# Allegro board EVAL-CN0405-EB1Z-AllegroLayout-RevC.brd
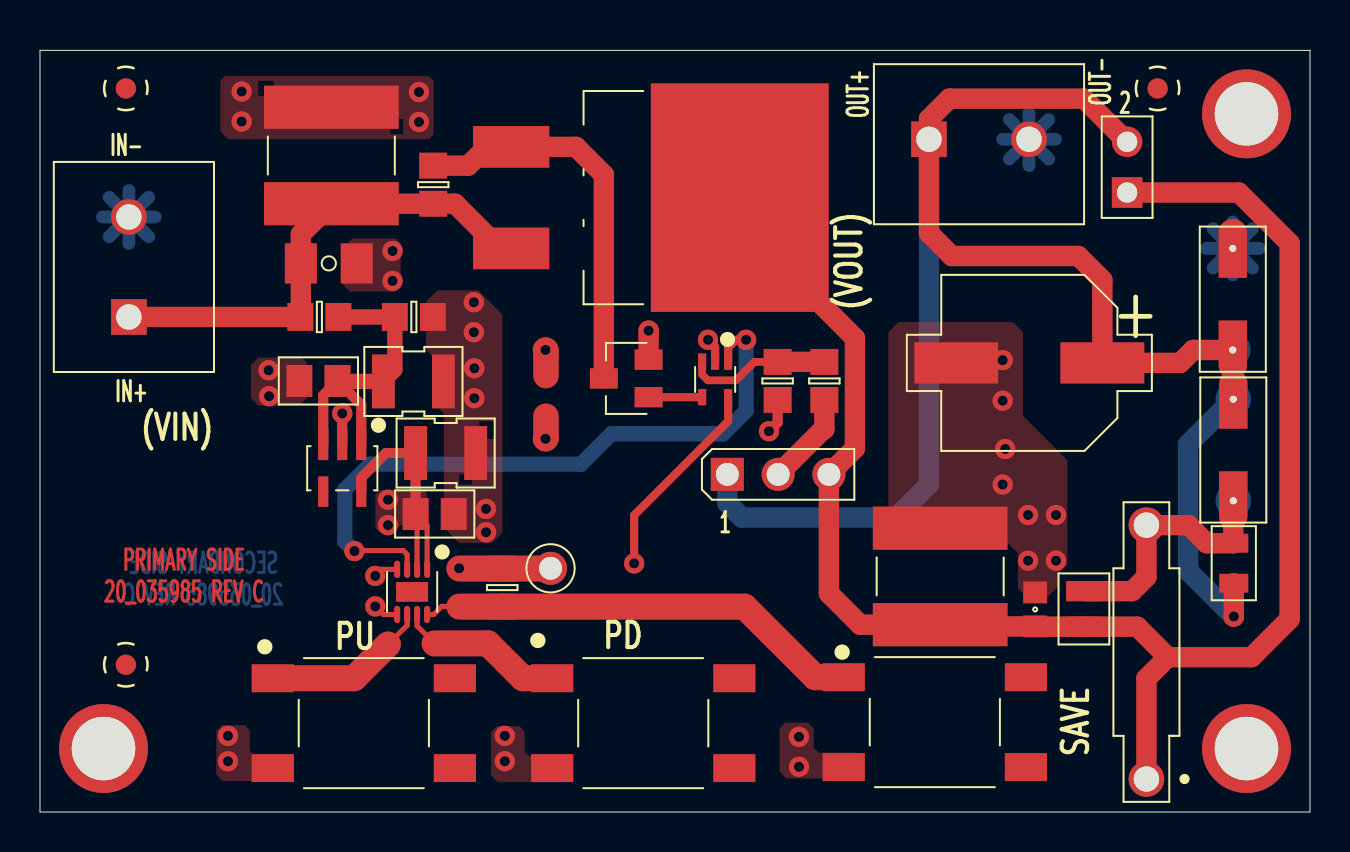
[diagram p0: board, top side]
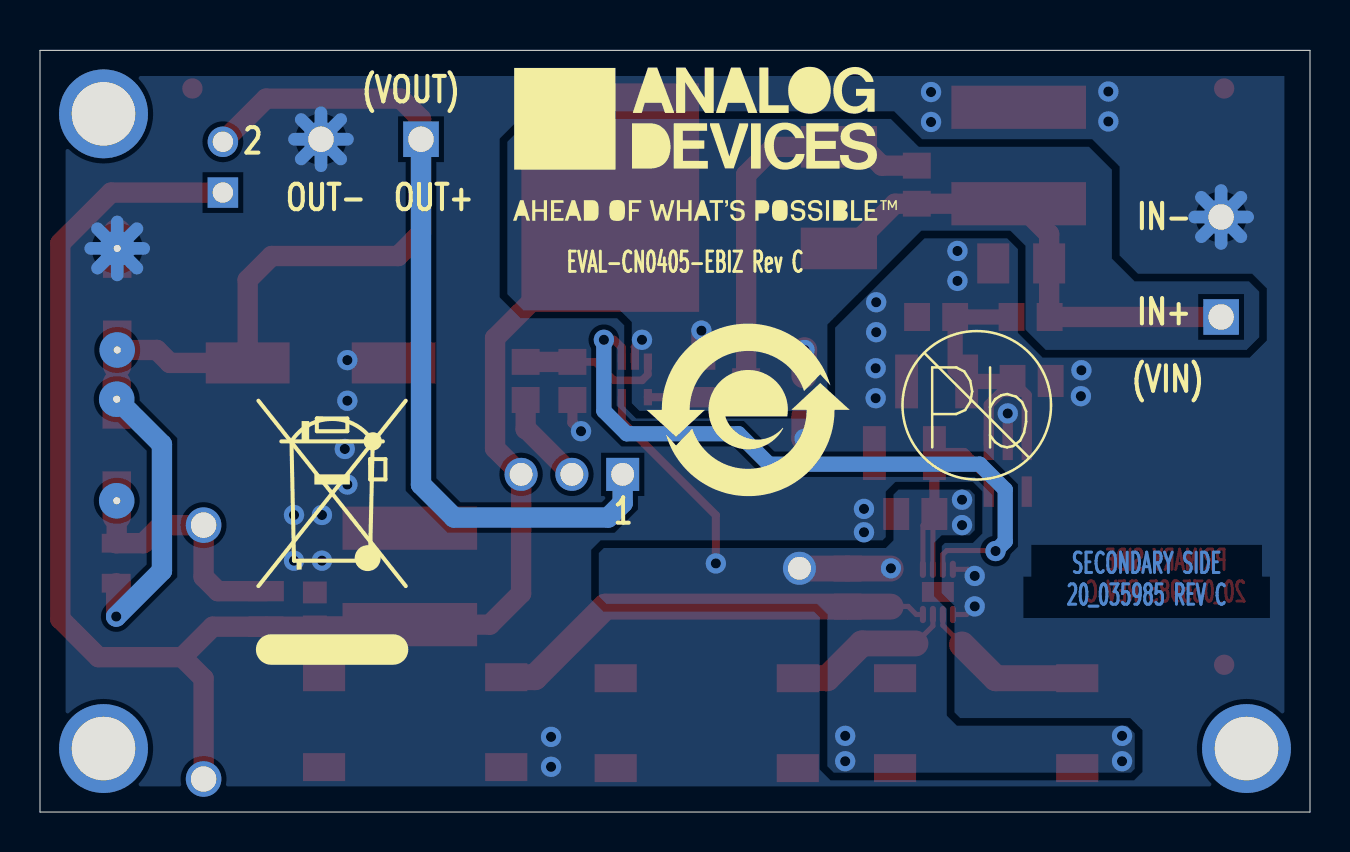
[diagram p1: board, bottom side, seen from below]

Outline 63.5 x 38.1 mm; copper layers: TOP, BOTTOM. Coordinates in mm from the lower left corner of the outline.
Outline path: 0,38.1 0,0 63.5,0 63.5,38.1 0,38.1

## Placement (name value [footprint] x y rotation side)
A1  ADCMP371AKSZ  [SC70-5]  33.76 21.64 180 top
C1  1uF  [C1210H75]  18.67 21.54 180 top
C2  0.1uF  [C0805H53]  13.92 21.56 0 top
C3  1uF  [C2225]  14.57 32.84 270 top
C4  0.1uF  [C1206H71]  14.44 27.44 180 top
C5  1uF  [C1210H75]  20.28 17.96 180 top
C6  0.1uF  [C0805H53]  19.74 14.91 180 top
C7  1uF  [C2225]  45.01 11.79 270 top
C8  0.1uF  [C0603]  49.76 10.13 90 top
C9  TBDR0805_CTH200LD25  [R0805_CTH200LD25]  59.64 28.19 270 top
C10  330UF  [CPLSMSQ327H413]  49.47 22.47 180 top
JP1  69157-102HLF  [CNBERG69157-102]  54.36 30.99 90 top
L1  330nH  [L9075]  52.2 10.16 90 top
L_G1  TBD_SPACER_500_D40  [L_SPACER_500_D40]  55.32 8 90 top
NOREF  -  []  0 36.41 0 top
NOREF#2  -  []  4.29 36.2 0 top
NOREF#3  -  []  -182.88 -240.03 0 top
NOREF#4  -  []  0 0 0 top
NOREF#5  -  []  -184.15 -241.3 0 top
NOREF#6  -  []  63.5 0 90 top
NOREF#7  -  [unnamed#2]  3.18 3.17 90 top
NOREF#8  -  [unnamed#2]  60.33 3.17 90 top
NOREF#9  -  [unnamed#2]  4.29 36.2 0 top
NOREF#10  -  [unnamed#2]  4.29 7.37 0 top
NOREF#11  -  []  32.23 51.59 0 top
NOREF#12  -  [unnamed#2]  55.88 36.2 0 top
NOREF#13  -  []  -175.26 -230.89 0 top
NOREF#14  -  []  0 38.1 270 top
NOREF#15  -  []  222 54.99 0 top
NOREF#16  -  []  63.5 0 90 top
NOREF#17  -  [unnamed#2]  60.33 34.92 90 top
NOREF#18  -  []  180.21 244.98 0 top
NOREF#19  -  []  4.29 36.2 90 top
NOREF#20  -  []  4.29 36.2 0 top
NOREF#21  -  []  -67.06 178.44 0 top
NOREF#22  -  []  63.5 38.1 180 top
NOREF#23  -  []  0 0 0 top
NOREF#24  -  []  28.09 20.12 180 bottom
NOREF#25  -  []  39.62 24.26 180 bottom
NOREF#26  -  []  30.23 33.4 180 bottom
NOREF#27  -  []  16.66 20.35 180 bottom
P1  CTB5000/2  [CN1X2H394]  4.45 24.77 90 top
P2  CTB5000/2  [CN1X2H394]  44.45 33.66 0 top
P3  TSW-103-08-G-S  [CNBERG1X3H205LD36]  34.37 16.89 0 top
Q1  BSS138LT1G  [SOT23]  29.31 21.69 90 top
Q2  IRF9630SPBF  [D2PAK]  30.54 30.73 270 top
R1  1.15K  [R0805]  13.97 24.77 180 top
R2  350  [R0805]  18.69 24.77 180 top
R3  1K  [R0805]  19.66 31.38 90 top
R4  80.6K  [R0805]  39.22 21.56 270 top
R5  13K  [R0805]  36.88 21.56 90 top
R6  100K  [R0805]  23.11 11.23 90 top
R7  TBDR0805_CTH200LD25  [R0805_CTH200LD25]  59.66 15.57 90 top
R8  50  [R0805H20]  59.69 12.45 270 top
S1  FSM8JSMAATR  [SWSMSQ236H384]  44.74 4.5 270 top
S2  FSM8JSMAATR  [SWSMSQ236H384]  30.16 4.45 270 top
S3  FSM8JSMAATR  [SWSMSQ236H384]  16.19 4.45 270 top
SNS1  SNS  [NCSNS50MIL]  25.3 19.8 90 top
TPVDD  TESTPAD  [TPC65D45]  25.53 12.19 0 top
U1  ADP121-AUJZ33  [TSOT-5]  15.11 17.2 180 top
U2  AD5116BCPZ5  [QFN8_2X2_PAD1_6X1]  18.61 11.01 180 top

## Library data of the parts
A1 = ADCMP37X: Tolerance: N/A; User Part Number: UPN; alternate symbols: (); part number: ADCMP37X_SM-ADCMP371AKSZ,E018321,SC70-5; tolerance: N/A
C1 C5 = CAP: User Part Number: UPN; Tolerance: 10; alternate symbols: (); part number: CAP_SM-1UF,50V,10,E017543,C1210H75; tolerance: 10
C2 C6 = CAP: Tolerance: 10; User Part Number: UPN; alternate symbols: (); part number: CAP_SM-0.1UF,50V,10,E010137,C0805H53; tolerance: 10
C3 C7 = CAP: Tolerance: 10; User Part Number: UPN; alternate symbols: (); part number: CAP_SM-1UF,200V,10,E012508,C2225; tolerance: 10
C4 = CAP: Tolerance: 10; User Part Number: UPN; alternate symbols: (); part number: CAP_SM-0.1UF,200V,10,E017225,C1206H71; tolerance: 10
C8 = CAP: Tolerance: 10; User Part Number: UPN; alternate symbols: (); part number: CAP_SM-0.1UF,10V,10,E018346,C0603; tolerance: 10
C9 = CAP: User Part Number: UPN; alternate symbols: (); part number: CAP_TH-TBDR0805_CTH200LD25,TBDR0805_CTH200LD25,TBDR0805_CTH200LD25,E016990,R0805_CTH200LD25
C10 = CAPP: User Part Number: UPN; Tolerance: 20; alternate symbols: (); part number: CAPP_SM-330UF,25V,20,E027963,CPLSMSQ327H413; tolerance: 20
JP1 = CNJMPRSHRT: Tolerance: N/A; User Part Number: UPN; alternate symbols: (); part number: CNJMPRSHRT_TH-69157-102HLF,E017268,CNBERG69157-102; tolerance: N/A
L1 = IND: Tolerance: 2; User Part Number: UPN; alternate symbols: (); part number: IND_SM-330NH,2,E007962,L9075; tolerance: 2
L_G1 = IND_V2: Tolerance: N/A; User Part Number: UPN; alternate symbols: (); part number: IND_V2_TH-TBD_SPACER_500_D40,N/A,E011375,L_SPACER_500_D40; tolerance: N/A
P1 P2 = CN2P: Tolerance: N/A; User Part Number: UPN; alternate symbols: (); part number: CN2P_TH-CTB5000/2,E017604,CN1X2H394; tolerance: N/A
P3 = CN3P: User Part Number: UPN; Tolerance: N/A; alternate symbols: (); part number: CN3P_TH-TSW-103-08-G-S,E000812,CNBERG1X3H205LD36; tolerance: N/A
Q1 = TRANNMOSFET_V8: User Part Number: UPN; Tolerance: N/A; alternate symbols: (); part number: TRANNMOSFET_V8_SM-BSS138LT1G,E018770,SOT23; tolerance: N/A
Q2 = TRANPMOSFET_V11: Tolerance: N/A; User Part Number: UPN; alternate symbols: (); part number: TRANPMOSFET_V11_SM-IRF9630SPBF,E020172,D2PAK; tolerance: N/A
R1 = RES: Tolerance: 1; User Part Number: UPN; alternate symbols: (); part number: RES_SM-1.15K,E003531,1/8W,1,R0805; tolerance: 1
R2 = RES: Tolerance: 0.01; User Part Number: UPN; alternate symbols: (); part number: RES_SM-350,E016531,1/5W,0.01,R0805; tolerance: 0.01
R3 = RES: Tolerance: 1; User Part Number: UPN; alternate symbols: (); part number: RES_SM-1K,E003415,1/8W,1,R0805; tolerance: 1
R4 = RES: Tolerance: 1; User Part Number: UPN; alternate symbols: (); part number: RES_SM-80.6K,E015510,1/8W,1,R0805; tolerance: 1
R5 = RES: Tolerance: 1; User Part Number: UPN; alternate symbols: (); part number: RES_SM-13K,E003507,1/8W,1,R0805; tolerance: 1
R6 = RES: Tolerance: 1; User Part Number: UPN; alternate symbols: (); part number: RES_SM-100K,E003488,1/8W,1,R0805; tolerance: 1
R7 = RES: User Part Number: UPN; alternate symbols: (); part number: RES_TH-TBDR0805_CTH200LD25,E016991,TBDR0805_CTH200LD25,TBDR0805_CTH200LD25,R0805_CTH200LD25
R8 = RES: Tolerance: 1; User Part Number: UPN; alternate symbols: (); part number: RES_SM-50,E026102,1/8W,1,R0805H20; tolerance: 1
S1-S3 = SWSPST4PIN_B: User Part Number: UPN; Tolerance: N/A; alternate symbols: (); part number: SWSPST4PIN_B_SM-FSM8JSMAATR,E018827,SWSMSQ236H384; tolerance: N/A
SNS1 = NCSENSE: User Part Number: UPN; Tolerance: N/A; alternate symbols: (); part number: NCSENSE_SM-SNS,E005619,NCSNS50MIL; tolerance: N/A
TPVDD = NCTESTPAD: Tolerance: N/A; User Part Number: UPN; alternate symbols: (); part number: NCTESTPAD_TH-TESTPAD,E013404,TPC65D45; tolerance: N/A
U1 = ADP121: User Part Number: UPN; Tolerance: N/A; alternate symbols: (); part number: ADP121_SM-ADP121-AUJZ33,E013943,TSOT-5; tolerance: N/A
U2 = AD511X: User Part Number: UPN; Tolerance: N/A; alternate symbols: (); part number: AD511X_SM-AD5116BCPZ5,E017320,QFN8_2X2_PAD1_6X1; tolerance: N/A

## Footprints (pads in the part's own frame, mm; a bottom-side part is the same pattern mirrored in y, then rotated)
C0603
  rect 1.092x1.194 smd: 1(-0.851,0) 2(0.851,0)
C0805H53
  rect 1.295x1.6 smd: 1(-0.953,0) 2(0.953,0)
C1206H71
  rect 1.6x2.007 smd: 1(-1.397,0) 2(1.397,0)
C1210H75
  rect 1.143x2.692 smd: 1(-1.501,0) 2(1.501,0)
C2225
  rect 2.159x6.731 smd: 1(-2.413,0) 2(2.413,0)
CN1X2H394
  rect 1.778x1.778 hole 1.27: 1(0,0)
  round 1.778 hole 1.27: 2(5.001,0)
CNBERG1X3H205LD36
  rect 1.651x1.651 hole 1.143: 1(0,0)
  round 1.651 hole 1.143: 2(2.54,0) 3(5.08,0)
CNBERG69157-102
  rect 1.524x1.524 hole 1.016: 1(0,0)
  round 1.524 hole 1.016: 2(2.54,0)
CPLSMSQ327H413
  rect 4.191x2.057 smd: N(3.65,0) P(-3.65,0)
D2PAK
  rect 2.083x3.81 smd: 1(-2.54,-6.985) 3(2.54,-6.985)
  rect 11.43x8.89 smd: 4(0,4.445)
L9075
  rect 1.016x1.778 smd: 1(-0.889,0) 2(0.889,0)
L_SPACER_500_D40
  round 1.778 hole 1.27: 1(-6.35,0) 2(6.35,0)
NCSNS50MIL
  round 0.127 smd: 1(0,0) 2(2.032,0)
QFN8_2X2_PAD1_6X1
  oval 0.305x0.864 smd: 1(-0.749,-1.13) 2(-0.249,-1.13) 3(0.249,-1.13) 4(0.749,-1.13) 5(0.749,1.13) 6(0.249,1.13) 7(-0.249,1.13) 8(-0.749,1.13)
  rect 1.6x0.991 smd: PAD(0,0)
R0805
  rect 1.295x1.397 smd: 1(-0.953,0) 2(0.953,0)
R0805_CTH200LD25
  custom 0.356x0.356 hole 1.27: 1(0,0) 2(5.08,0)
R0805H20
  rect 0.94x1.448 smd: 1(-1.001,0) 2(1.001,0)
SC70-5
  rect 0.406x0.813 smd: 1(-0.65,-0.889) 2(0,-0.889) 3(0.65,-0.889) 4(0.65,0.889) 5(-0.65,0.889)
SOT23
  rect 1.016x1.397 smd: 1(-0.94,-1.118) 2(0.94,-1.118) 3(0,1.118)
SWSMSQ236H384
  rect 1.397x2.108 smd: 1(-2.248,-4.554) 2(-2.248,4.554) 3(2.248,-4.554) 4(2.248,4.554)
TPC65D45
  round 1.651 hole 1.143: 1(0,0)
TSOT-5
  rect 0.508x1.524 smd: 1(-0.95,-1.171) 2(0,-1.171) 3(0.95,-1.171) 4(0.95,1.171) 5(-0.95,1.171)
unnamed#2
  round 4.445 hole 3.175 unplated: (0,0)

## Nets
AGND: C1.1(N1) C2.1(N1) C3.1(N1) C4.1(N1) C5.1(N1) C6.1(N1) C7.1(N1) C8.2(N2) C9.1(N1) C10.N(N2) P1.2(N2) P2.2(N2) R2.1(N1) R5.1(N1) S1.3(N3) SNS1.1(N1) U1.2(GND) U2.4(B) U2.5(GND)
DGND: A1.2(GND) Q1.2(S) SNS1.2(N2)
VDD: A1.5(VCC) C5.2(N2) C6.2(N2) R6.2(N2) S2.3(N3) S3.3(N3) TPVDD.1(N1) U1.5(VOUT) U2.1(VDD) U2.2(A)
ASE: R6.1(N1) S1.1(N1) U2.8(ASE_N)
PD: S3.1(N1) U2.6(PD)
PU: S2.1(N1) U2.7(PU)
UNNAMED_2_AD511X_I16_W: A1.1(IN+) U2.3(W)
UNNAMED_2_ADCMP37X_I57_IN: A1.3(IN-) R4.1(N1) R5.2(N2)
UNNAMED_2_ADCMP37X_I57_OUT: A1.4(OUT) Q1.1(G)
UNNAMED_2_ADP121_I14_EN: C1.2(N2) C2.2(N2) R1.1(N1) R2.2(N2) U1.1(VIN) U1.3(EN)
UNNAMED_2_CAP_I50_N2: C3.2(N2) C4.2(N2) P1.1(N1) Q2.3(S) R1.2(N2) R3.1(N1)
UNNAMED_2_CAP_I55_N2: C7.2(N2) C8.1(N1) JP1.1(S1) L1.1(N1) L_G1.1(N1) P3.3(N3) Q2.4(D)
UNNAMED_2_CN2P_I25_N1: C9.2(N2) C10.P(N1) JP1.2(S2) P2.1(N1) P3.1(N1) R7.2(N2) R8.2(N2)
UNNAMED_2_IND_I89_N2: L1.2(N2) L_G1.2(N2) R7.1(N1) R8.1(N1)
UNNAMED_2_RES_I34_N2: P3.2(N2) R4.2(N2)
UNNAMED_2_RES_I85_N2: Q1.3(D) Q2.1(G) R3.2(N2)

Pads without a net: S1 2 4; S2 2 4; S3 2 4; U1 4; U2 PAD

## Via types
v1: diameter 1.016, hole 0.508, TOP to BOTTOM, 43 vias

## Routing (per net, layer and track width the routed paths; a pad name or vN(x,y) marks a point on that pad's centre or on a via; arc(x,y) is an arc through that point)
AGND: length 39.5
  TOP w0.254: v1(16.76,10.29) 17.17,9.88 U2.5 ; v1(16.76,11.81) 17.09,12.14 U2.4
  TOP w0.508: v1(36.45,19.05) 36.88,19.48 R5.1 ; U1.2 v1(15.11,19.94)
  TOP w1.27: v1(25.27,18.67) 25.3,18.69 SNS1.1
  BOTTOM w0.635: 48.13,33.66 P2.2 ; P2.2 50.44,32.67 ; P2.2 50.77,33.66 ; P2.2 50.44,34.64 ; P2.2 49.45,34.98 ; P2.2 48.47,34.64 ; P2.2 49.45,32.33 ; P2.2 48.47,32.67 ; P1.2 5.43,30.75 ; P1.2 4.45,31.09 ; P1.2 3.12,29.77 ; P1.2 5.77,29.77 ; P1.2 3.46,28.78 ; P1.2 4.45,28.44 ; P1.2 5.43,28.78 ; P1.2 3.46,30.75 ; 58.65,29.18 C9.1 ; C9.1 59.64,29.52 ; C9.1 60.62,27.21 ; C9.1 59.64,26.87 ; C9.1 58.32,28.19 ; C9.1 60.96,28.19 ; C9.1 58.65,27.21 ; C9.1 60.62,29.18
  vias: v1(10.08,36.04) v1(10.08,34.54) v1(11.43,22.1) v1(11.46,20.8) v1(17.63,28.07) v1(17.63,26.57) v1(18.95,36.02) v1(18.95,34.52) v1(21.69,25.5) v1(21.69,24) v1(21.72,22.2) v1(21.72,20.7) v1(22.3,15.16) v1(22.3,14) v1(37.95,3.76) v1(37.95,2.26) v1(48.13,22.61) v1(48.13,20.57) v1(48.13,16.38) v1(48.26,18.16) v1(49.4,14.86) v1(49.4,12.57) v1(50.8,14.86) v1(50.8,12.57)
DGND: length 4
  TOP w0.406: A1.2 33.76,23.27 v1(33.4,23.62)
  TOP w1.016: Q1.2 v1(30.43,24.08)
  TOP w1.27: v1(25.27,23.11) 25.3,23.09 SNS1.2
VDD: length 27.5
  TOP w0.254: 18.85,14.84 C6.2 ; 18.85,14.84 U2.2 ; 18.85,14.84 19.35,14.34 U2.1
  TOP w0.406: v1(29.71,12.44) 29.71,14.85 34.41,19.55 A1.5
  TOP w0.508: 18.78,14.91 C5.2 17.3,17.96 16.06,16.72 U1.5
  TOP w0.635: C6.2 18.78,14.91
  TOP w0.762: 20.97,12.18 v1(20.96,12.19)
  TOP w1.295: 20.97,12.18 R6.2 25.51,12.18 TPVDD.1
  vias: v1(9.4,3.81) v1(9.4,2.54) v1(17.4,15.62) v1(17.4,14.35) v1(23.24,3.81) v1(23.24,2.54)
ASE: length 22.5
  TOP w0.254: U2.8 19.69,9.88 20.09,10.29 20.96,10.29 20.97,10.27
  TOP w1.295: S1.1 38.76,6.74 35.23,10.27 R6.1 20.97,10.27
PD: length 8.4
  TOP w0.254: 17.4,8.38 18.36,9.34 U2.6
  TOP w1.295: 17.4,8.38 15.71,6.69 S3.1
PU: length 8.4
  TOP w0.254: U2.7 18.85,9.31 19.73,8.43
  TOP w1.295: S2.1 24.14,6.69 22.4,8.43 19.73,8.43
UNNAMED_2_AD511X_I16_W: length 33.8
  TOP w0.254: U2.3 18.36,12.89 18.16,13.08 15.75,13.08 v1(15.72,13.06)
  TOP w0.406: A1.1 34.41,23.23 34.8,23.62 v1(35.31,23.62)
  BOTTOM w0.762: v1(35.31,23.62) 35.31,20.07 34.16,18.92 28.57,18.92 27.05,17.4 16.51,17.4 15.24,16.13 15.24,13.54 v1(15.72,13.06)
UNNAMED_2_ADCMP37X_I57_IN: length 7.3
  TOP w0.381: R5.2 35.72,22.52 34.8,21.6 33.4,21.6 33.11,21.88 A1.3
  TOP w1.016: R4.1 R5.2
UNNAMED_2_ADCMP37X_I57_OUT: length 2.7
  TOP w0.406: A1.4 Q1.1
UNNAMED_2_ADP121_I14_EN: length 15.7
  TOP w0.508: 14.9,21.54 16.06,20.37 U1.1 ; U1.3 14.16,20.86 C2.2
  TOP w0.762: R1.1 R2.2 17.74,22.11 C1.2 14.9,21.54 C2.2
UNNAMED_2_CAP_I50_N2: length 24.8
  TOP w1.016: 23.56,28.19 22.99,28.19 20.75,30.43 R3.1 C3.2 13.04,28.91 C4.2 13.04,24.79 R1.2 P1.1
UNNAMED_2_CAP_I55_N2: length 82.4
  TOP w1.016: 56.39,7.75 60.58,7.75 62.48,9.65 62.48,28.45 59.94,30.99 JP1.1 ; 56.39,7.75 54.86,9.27 L1.1 49.77,9.27 C8.1 45.1,9.28 C7.2 41.01,9.37 39.45,10.93 P3.3 40.75,18.19 40.75,23.71 34.99,29.46 Q2.4 ; 56.39,7.75 55.32,6.68 L_G1.1
UNNAMED_2_CN2P_I25_N1: length 84.2
  TOP w1.016: R8.2 v1(59.69,9.78) ; R7.2 59.66,23.09 C9.2 57.66,23.11 57.01,22.47 C10.P 53.12,26.61 51.92,27.81 45.59,27.81 44.45,28.96 P2.1 44.45,34.67 45.47,35.69 52.2,35.69 JP1.2
  BOTTOM w1.016: P2.1 44.45,16.38 42.8,14.73 35.09,14.73 34.37,15.46 P3.1 ; R7.2 57.4,18.39 57.4,12.07 v1(59.69,9.78)
UNNAMED_2_IND_I89_N2: length 12.9
  TOP w1.016: R7.1 59.66,13.47 R8.1 58.33,13.45 57.43,14.35 L_G1.2 55.32,11.76 54.61,11.05 L1.2
UNNAMED_2_RES_I34_N2: length 4.7
  TOP w1.016: P3.2 39.17,19.15 39.22,19.15 R4.2
UNNAMED_2_RES_I85_N2: length 19.7
  TOP w1.016: Q1.3 28.19,31.88 26.8,33.27 22.35,33.27 21.41,32.33 R3.2

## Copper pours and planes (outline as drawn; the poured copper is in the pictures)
AGND on TOP: 15.62,28.7 17.78,28.7 18.03,28.45 18.03,26.29 17.78,26.04 15.49,26.04 15.11,26.42 15.11,28.19
AGND on TOP: 37.26,4.47 38.4,4.47 38.68,4.19 38.68,3.23 38.94,2.97 40.79,2.97 41,2.77 41,1.93 40.74,1.68 37.31,1.68 36.98,2.01 36.98,4.19
AGND on TOP: 51.37,12.38 50.93,11.94 50.93,11.3 50.42,10.8 49.28,10.8 48.9,11.18 48.9,12.95 48.39,13.46 43.05,13.46 42.42,14.1 42.42,24 42.93,24.51 48.64,24.51 49.15,24 49.15,19.81 51.37,17.59
AGND on TOP: 13.08,22.73 13.34,22.48 13.34,20.7 12.95,20.32 10.92,20.32 10.54,20.7 10.54,22.35 10.92,22.73
AGND on TOP: 9.4,33.66 9.02,34.04 9.02,36.57 9.27,36.83 19.43,36.83 19.69,36.58 19.69,33.91 19.43,33.66 ; 2 cut-outs
AGND on TOP: 21.91,26.1 23.11,24.89 23.11,13.97 22.61,13.46 20.96,13.46 20.19,14.22 20.19,19.94 19.69,20.45 19.69,22.73 19.3,23.11 19.3,25.53 19.88,26.1 ; 2 cut-outs
AGND on BOTTOM: 1.28,1.28 1.28,36.82 62.22,36.82 62.22,1.28
DGND on BOTTOM: 3.05,26.54 8.76,26.54 9.91,27.69 9.91,32.13 11.05,33.27 19.56,33.27 20.96,34.67 38.99,34.67 40.13,33.53 40.13,25.91 39.31,25.08 34.48,25.08 33.91,24.51 33.91,20.45 33.53,20.07 24.51,20.07 24.13,20.45 24.13,24.38 19.43,29.08 14.99,29.08 14.22,28.32 14.22,24.13 13.21,23.11 3.18,23.11 2.54,23.75 2.54,26.04
VDD on TOP: 22.83,4.29 23.98,4.29 24.23,4.04 24.23,3.02 24.46,2.79 26.37,2.79 26.57,2.59 26.57,1.75 26.31,1.5 22.89,1.5 22.56,1.83 22.56,4.01
VDD on TOP: 17.02,16.12 19.19,16.12 19.33,15.98 19.33,14.5 19.18,14.35 18.03,14.35 17.64,13.96 17.02,13.96 16.77,14.21 16.77,15.87
VDD on TOP: 9.09,4.34 10.24,4.34 10.49,4.09 10.49,3.07 10.72,2.84 12.4,2.84 12.57,2.67 12.57,1.7 12.42,1.55 9.14,1.55 8.81,1.88 8.81,4.06
VDD on BOTTOM: 8.76,2.16 8.76,3.94 9.14,4.32 17.65,4.32 18.16,4.83 18.16,10.16 18.8,10.8 18.8,13.46 18.41,13.84 17.02,13.84 16.76,14.1 16.76,15.88 17.02,16.13 20.57,16.13 20.83,15.88 20.83,13.59 21.21,13.21 35.31,13.21 35.56,12.95 35.56,10.8 35.18,10.41 24.64,10.41 24.13,9.91 24.13,2.29 23.81,1.97 8.95,1.97

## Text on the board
BOTTOM: SECONDARY SIDE | 20_035985 REV C
Ref Des/Silkscreen Bottom: EVAL-CN0405-EBIZ Rev C | (VIN) | IN- | IN+ | OUT+ | (VOUT) | OUT-
TOP: PRIMARY SIDE | 20_035985 REV C
Ref Des/Silkscreen Top: IN- | IN+ | OUT+ | OUT- | (VIN) | PU | PD | (VOUT) | SAVE
PAGE_OUTLINE: 0.062" THICK LAYERED MATERIAL | PER NOTES/STACK UP | TWO STAGE FLASH GOLD | OVER NICKEL | N/A | 15MAY13 | 21MAY13 | NOV12 | C | B | AS PER ECR-066032 | AS PER ECR-045118 | AS PER ECR-066444 | AS PER ECR-065199 | 02JAN17 | 07DEC16 | 27OCT16 | 17FEB14 | D. RICE | J. RODRIQUEZ | NOTES: | 1. THE BOARD SIZE MAY VARY TO COMPENSATE THE COMPONENTS DENSITY OF THE CIRCUIT. | 2. THE BOARD MAY EXTEND TO THE RIGHT AND LOWER PORTION IF THERE IS A NEED TO CHANGE THE BOARD SIZE. | 3. J1 CONNECTOR LOCATION IS FIXED WITH REFERENCE TO THE DISTANCE ON BOARD EDGE ON THE UPPER LEFT PORTION.
DIMENSION: (REF) | +DIA MAX | +/- 3 MILS | +/- 2 MILS
DISPLAY_BOTTOM: L2 GND | 08-      -07
User.6: L3 POWER | 08-      -08
User.17: 1. CHANGE R3 TO 1K; R5 TO 13K. | 3. MODIFY Q2 FOR NEW COMPONENT. | 2. ADD SMALL DNI TESTPOINT TO VDD AND NAMED VDD. | 4. ADD MODEL NAME EVAL-CN0405-EB1Z AS CFTL BOARD. | 4. CHANGE R1 TO 1.15K, R2 TO 350OHM AND R3 TO 100K. | 6. CHANGE C10 VALUE FROM MFG#25CE330PC TO MFG#25CE330AX. | 3. ADD ADDITIONAL LABEL TO P1 AS PI (VIN) AND P2 AS P2 (VOUT). | 2. SWITCH +/- TERMINALS ON A1 (ADCMP320), RESISTOR AND INDUCTOR. | THE FOLLOWING CHANGES WERE MADE TO REV.B BOARDS TO BRING THEM TO REV.C: | THE FOLLOWING CHANGES WERE MADE TO REV.A BOARDS TO BRING TEHEM TO REV.B: | 1. ADD FOOTPRINTS FOR NEW FILTER CAPACITOR, RESISTOR AND INDUCTOR. | 5. CHANGE R8 VALUE FROM 1K OHM TO 50 OHM; C10 FROM 1uF (DNI) TO 330uF INSTALLED. | 5. ADD 2 OPTION JUMPER TO GIVE USER THE OPTION OF BYPASSING THE NEW FILTER COMPONENTS. | 1 | 13 | REWORK | A
User.19: ASSEMBLY INSTRUCTION | 1. L_G1,R7 and C9 to be installed with M013346 gold wire wrap.
User.27: FIGURE | SIZE | 20.0 | 40.0 | 45.0 | 50.0 | 125.0 | TOLERANCE | +3.0/-3.0 | +2.0/-2.0 | DRILL CHART: TOP to BOTTOM | FINISHED HOLES IN MILS | PLATED | NON-PLATED | QTY | 43 | 2 | 1 | 3 | 6 | 4 | TOLERANCE/NOTES
